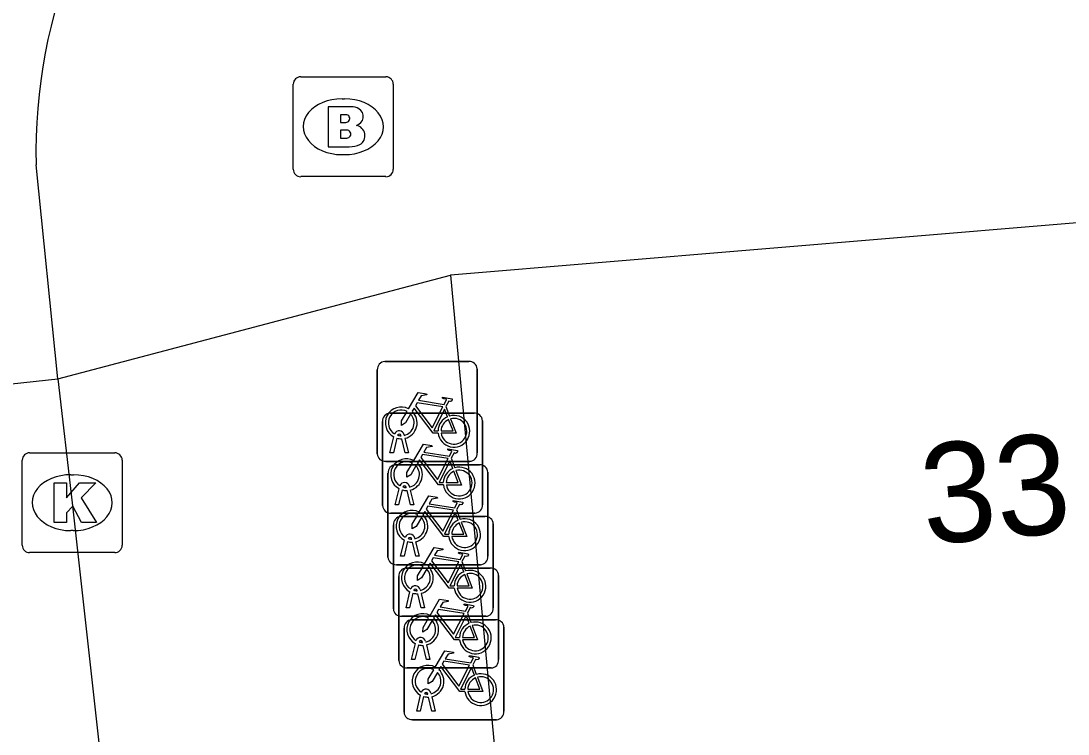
# Model space of a CAD drawing. Extents: x 159961 to 160856, y 382704 to 383353.
# Drawn here: x 160072.17 to 160082.65, y 383277.5 to 383284.64 of the extents above; entities that cross this region are included whole.
import ezdxf

# ---------------------------------------------------------------- set-up
doc = ezdxf.new("R2010")
doc.units = 0
for name, color, linetype in [('IMGEO_Brandkraan', 7, 'Continuous'), ('IMGEO_Fietsenrek', 7, 'Continuous'), ('IMGEO_Kolk', 7, 'Continuous'), ('IMGEO_Pand', 7, 'Continuous'), ('IMGEO_Pand_nummerreeks', 7, 'Continuous'), ('IMGEO_Rijbaan_lokaal_open', 7, 'Continuous'), ('IMGEO_Voetpad_open', 7, 'Continuous')]:
    doc.layers.add(name, color=color, linetype=linetype)

msp = doc.modelspace()

# ---------------------------------------------------------------- linework, layer by layer
at = {"layer": 'IMGEO_Brandkraan'}
for p, q in [((160074.897, 383283.157), (160074.897, 383284.009)), ((160074.972, 383284.083), (160075.824, 383284.083)), ((160075.898, 383284.009), (160075.898, 383283.157)), ((160075.385, 383283.863), (160075.41, 383283.863)), ((160075.408, 383283.303), (160075.383, 383283.303)), ((160075.824, 383283.083), (160074.972, 383283.083))]:
    msp.add_line(p, q, dxfattribs=at)
for points in [[(160074.897, 383283.157), (160074.897, 383284.009)], [(160074.972, 383284.083), (160075.824, 383284.083)], [(160075.898, 383284.009), (160075.898, 383283.157)], [(160075.245, 383283.783), (160075.245, 383283.383), (160075.458, 383283.383)], [(160075.476, 383283.783), (160075.245, 383283.783)], [(160075.424, 383283.702), (160075.37, 383283.702), (160075.37, 383283.626)], [(160075.37, 383283.626), (160075.423, 383283.626)], [(160075.432, 383283.55), (160075.37, 383283.55), (160075.37, 383283.469)], [(160075.37, 383283.469), (160075.432, 383283.469)], [(160075.824, 383283.083), (160074.972, 383283.083)]]:
    msp.add_lwpolyline(points, dxfattribs=at)
for centre, radius, start, end in [((160074.974, 383284.007), 0.0765, 91.552, 178.448), ((160074.974, 383284.007), 0.0765, 91.552, 178.448), ((160075.822, 383284.007), 0.0765, 1.552, 88.448), ((160075.822, 383284.007), 0.0765, 1.552, 88.448), ((160075.425, 383283.664), 0.0379, 267.8285, 90.9355), ((160075.48, 383283.638), 0.145, 59.4692, 91.5367), ((160075.505, 383283.685), 0.0922, 285.5137, 58.1501), ((160075.51, 383283.493), 0.105, 301.3115, 78.989), ((160075.433, 383283.509), 0.0404, 269.8759, 90.5077), ((160075.464, 383283.634), 0.251, 268.6676, 293.5347), ((160074.974, 383283.159), 0.0765, 181.552, 268.448), ((160074.974, 383283.159), 0.0765, 181.552, 268.448), ((160075.822, 383283.159), 0.0765, 271.552, 358.448), ((160075.822, 383283.159), 0.0765, 271.552, 358.448)]:
    msp.add_arc(centre, radius, start, end, dxfattribs=at)
for centre, major_axis, ratio, start_param, end_param in [((160075.384, 383283.583), (-0.387, 0.002), 0.722429, 4.712389, 7.853982), ((160075.409, 383283.583), (-0.39, 0.002), 0.717154, 1.570796, 4.712389)]:
    msp.add_ellipse(centre, major_axis=major_axis, ratio=ratio, start_param=start_param, end_param=end_param, dxfattribs=at)
at = {"layer": 'IMGEO_Fietsenrek'}
for p, q in [((160075.813, 383281.232), (160076.654, 383281.232)), ((160076.654, 383281.232), (160075.813, 383281.232)), ((160075.738, 383280.307), (160075.738, 383281.148)), ((160075.738, 383281.148), (160075.738, 383280.307)), ((160076.738, 383281.157), (160076.738, 383280.316)), ((160076.738, 383280.316), (160076.738, 383281.157)), ((160076.425, 383280.781), (160076.461, 383280.686)), ((160075.866, 383280.714), (160076.707, 383280.714)), ((160076.707, 383280.714), (160075.866, 383280.714)), ((160075.791, 383279.789), (160075.791, 383280.63)), ((160075.791, 383280.63), (160075.791, 383279.789)), ((160076.791, 383280.639), (160076.791, 383279.798)), ((160076.791, 383279.798), (160076.791, 383280.639)), ((160075.865, 383280.316), (160075.904, 383280.476)), ((160075.934, 383280.464), (160075.899, 383280.316)), ((160075.976, 383280.488), (160075.975, 383280.492)), ((160076.017, 383280.316), (160075.983, 383280.458)), ((160076.007, 383280.499), (160076.008, 383280.492)), ((160076.015, 383280.462), (160076.05, 383280.316)), ((160075.899, 383280.316), (160075.865, 383280.316)), ((160076.05, 383280.316), (160076.017, 383280.316)), ((160076.478, 383280.263), (160076.514, 383280.168)), ((160076.663, 383280.232), (160075.822, 383280.232)), ((160075.822, 383280.232), (160076.663, 383280.232)), ((160075.92, 383280.197), (160076.761, 383280.197)), ((160076.761, 383280.197), (160075.92, 383280.197)), ((160075.845, 383279.272), (160075.845, 383280.113)), ((160075.845, 383280.113), (160075.845, 383279.272)), ((160076.845, 383280.122), (160076.845, 383279.281)), ((160076.845, 383279.281), (160076.845, 383280.122)), ((160075.918, 383279.798), (160075.957, 383279.958)), ((160075.987, 383279.946), (160075.952, 383279.798)), ((160076.029, 383279.97), (160076.028, 383279.974)), ((160076.07, 383279.798), (160076.036, 383279.94)), ((160076.06, 383279.981), (160076.061, 383279.974)), ((160076.068, 383279.944), (160076.103, 383279.798)), ((160076.716, 383279.714), (160075.875, 383279.714)), ((160075.875, 383279.714), (160076.716, 383279.714)), ((160075.952, 383279.798), (160075.918, 383279.798)), ((160076.103, 383279.798), (160076.07, 383279.798)), ((160076.532, 383279.746), (160076.568, 383279.651)), ((160075.974, 383279.68), (160076.815, 383279.68)), ((160076.815, 383279.68), (160075.974, 383279.68)), ((160076.899, 383279.605), (160076.899, 383278.764)), ((160076.899, 383278.764), (160076.899, 383279.605)), ((160075.899, 383278.755), (160075.899, 383279.596)), ((160075.899, 383279.596), (160075.899, 383278.755)), ((160075.972, 383279.281), (160076.011, 383279.441)), ((160076.041, 383279.429), (160076.006, 383279.281)), ((160076.083, 383279.453), (160076.082, 383279.457)), ((160076.124, 383279.281), (160076.09, 383279.423)), ((160076.114, 383279.464), (160076.115, 383279.457)), ((160076.122, 383279.427), (160076.157, 383279.281)), ((160076.77, 383279.197), (160075.929, 383279.197)), ((160075.929, 383279.197), (160076.77, 383279.197)), ((160076.006, 383279.281), (160075.972, 383279.281)), ((160076.157, 383279.281), (160076.124, 383279.281)), ((160076.586, 383279.229), (160076.622, 383279.134)), ((160076.028, 383279.163), (160076.869, 383279.163)), ((160076.869, 383279.163), (160076.028, 383279.163)), ((160076.953, 383279.088), (160076.953, 383278.247)), ((160076.953, 383278.247), (160076.953, 383279.088)), ((160075.953, 383278.238), (160075.953, 383279.079)), ((160075.953, 383279.079), (160075.953, 383278.238)), ((160076.026, 383278.764), (160076.065, 383278.924)), ((160076.095, 383278.912), (160076.06, 383278.764)), ((160076.137, 383278.936), (160076.136, 383278.94)), ((160076.178, 383278.764), (160076.144, 383278.906)), ((160076.168, 383278.947), (160076.169, 383278.94)), ((160076.176, 383278.91), (160076.211, 383278.764)), ((160076.824, 383278.68), (160075.983, 383278.68)), ((160075.983, 383278.68), (160076.824, 383278.68)), ((160076.06, 383278.764), (160076.026, 383278.764)), ((160076.211, 383278.764), (160076.178, 383278.764)), ((160076.64, 383278.712), (160076.676, 383278.617)), ((160076.006, 383277.72), (160076.006, 383278.561)), ((160076.006, 383278.561), (160076.006, 383277.72)), ((160076.081, 383278.645), (160076.922, 383278.645)), ((160076.922, 383278.645), (160076.081, 383278.645)), ((160077.006, 383278.57), (160077.006, 383277.729)), ((160077.006, 383277.729), (160077.006, 383278.57)), ((160076.08, 383278.247), (160076.119, 383278.407)), ((160076.149, 383278.395), (160076.114, 383278.247)), ((160076.191, 383278.419), (160076.19, 383278.423)), ((160076.232, 383278.247), (160076.198, 383278.389)), ((160076.222, 383278.43), (160076.223, 383278.423)), ((160076.23, 383278.393), (160076.265, 383278.247)), ((160076.114, 383278.247), (160076.08, 383278.247)), ((160076.265, 383278.247), (160076.232, 383278.247)), ((160076.878, 383278.163), (160076.037, 383278.163)), ((160076.037, 383278.163), (160076.878, 383278.163)), ((160076.693, 383278.194), (160076.729, 383278.099)), ((160076.133, 383277.729), (160076.172, 383277.889)), ((160076.202, 383277.877), (160076.167, 383277.729)), ((160076.244, 383277.901), (160076.243, 383277.905)), ((160076.285, 383277.729), (160076.251, 383277.871)), ((160076.275, 383277.912), (160076.276, 383277.905)), ((160076.283, 383277.875), (160076.318, 383277.729)), ((160076.167, 383277.729), (160076.133, 383277.729)), ((160076.318, 383277.729), (160076.285, 383277.729)), ((160076.931, 383277.645), (160076.09, 383277.645)), ((160076.09, 383277.645), (160076.931, 383277.645))]:
    msp.add_line(p, q, dxfattribs=at)
for points in [[(160076.051, 383280.758), (160076.146, 383280.922), (160076.232, 383280.908), (160076.234, 383280.899), (160076.178, 383280.888), (160076.151, 383280.843), (160076.407, 383280.802)], [(160076.407, 383280.802), (160076.432, 383280.851), (160076.426, 383280.855), (160076.403, 383280.859), (160076.391, 383280.866), (160076.39, 383280.869), (160076.392, 383280.874), (160076.487, 383280.859), (160076.489, 383280.849), (160076.479, 383280.836), (160076.467, 383280.83), (160076.453, 383280.836), (160076.425, 383280.781)], [(160076.347, 383280.514), (160076.297, 383280.514), (160076.106, 383280.765), (160076.087, 383280.733)], [(160076.394, 383280.777), (160076.137, 383280.818), (160076.12, 383280.789), (160076.287, 383280.569), (160076.394, 383280.777)], [(160076.072, 383280.706), (160076.02, 383280.616), (160075.98, 383280.591), (160075.981, 383280.638), (160076.036, 383280.732)], [(160076.442, 383280.679), (160076.412, 383280.756), (160076.303, 383280.538), (160076.346, 383280.538)], [(160076.472, 383280.658), (160076.527, 383280.513), (160076.377, 383280.513)], [(160076.376, 383280.538), (160076.496, 383280.537), (160076.452, 383280.651)], [(160076.104, 383280.24), (160076.199, 383280.404), (160076.285, 383280.39), (160076.287, 383280.381), (160076.231, 383280.37), (160076.204, 383280.325), (160076.46, 383280.284)], [(160076.46, 383280.284), (160076.485, 383280.333), (160076.479, 383280.337), (160076.456, 383280.341), (160076.444, 383280.348), (160076.443, 383280.351), (160076.445, 383280.356), (160076.54, 383280.341), (160076.542, 383280.331), (160076.532, 383280.318), (160076.52, 383280.312), (160076.506, 383280.318), (160076.478, 383280.263)], [(160076.4, 383279.996), (160076.35, 383279.996), (160076.159, 383280.247), (160076.14, 383280.215)], [(160076.447, 383280.259), (160076.19, 383280.3), (160076.173, 383280.271), (160076.34, 383280.051), (160076.447, 383280.259)], [(160076.495, 383280.161), (160076.465, 383280.238), (160076.356, 383280.02), (160076.399, 383280.02)], [(160076.125, 383280.188), (160076.073, 383280.098), (160076.033, 383280.073), (160076.034, 383280.12), (160076.089, 383280.214)], [(160076.429, 383280.02), (160076.549, 383280.019), (160076.505, 383280.133)], [(160076.525, 383280.14), (160076.58, 383279.995), (160076.43, 383279.995)], [(160076.158, 383279.723), (160076.253, 383279.887), (160076.339, 383279.873), (160076.341, 383279.864), (160076.285, 383279.853), (160076.258, 383279.808), (160076.514, 383279.767)], [(160076.514, 383279.767), (160076.539, 383279.816), (160076.533, 383279.82), (160076.51, 383279.824), (160076.498, 383279.831), (160076.497, 383279.834), (160076.499, 383279.839), (160076.594, 383279.824), (160076.596, 383279.814), (160076.586, 383279.801), (160076.574, 383279.795), (160076.56, 383279.801), (160076.532, 383279.746)], [(160076.454, 383279.479), (160076.404, 383279.479), (160076.213, 383279.73), (160076.194, 383279.698)], [(160076.501, 383279.742), (160076.244, 383279.783), (160076.227, 383279.754), (160076.394, 383279.534), (160076.501, 383279.742)], [(160076.549, 383279.644), (160076.519, 383279.721), (160076.41, 383279.503), (160076.453, 383279.503)], [(160076.179, 383279.671), (160076.127, 383279.581), (160076.087, 383279.556), (160076.088, 383279.603), (160076.143, 383279.697)], [(160076.483, 383279.503), (160076.603, 383279.502), (160076.559, 383279.616)], [(160076.579, 383279.623), (160076.634, 383279.478), (160076.484, 383279.478)], [(160076.212, 383279.206), (160076.307, 383279.37), (160076.393, 383279.356), (160076.395, 383279.347), (160076.339, 383279.336), (160076.312, 383279.291), (160076.568, 383279.25)], [(160076.568, 383279.25), (160076.593, 383279.299), (160076.587, 383279.303), (160076.564, 383279.307), (160076.552, 383279.314), (160076.551, 383279.317), (160076.553, 383279.322), (160076.648, 383279.307), (160076.65, 383279.297), (160076.64, 383279.284), (160076.628, 383279.278), (160076.614, 383279.284), (160076.586, 383279.229)], [(160076.508, 383278.962), (160076.458, 383278.962), (160076.267, 383279.213), (160076.248, 383279.181)], [(160076.555, 383279.225), (160076.298, 383279.266), (160076.281, 383279.237), (160076.448, 383279.017), (160076.555, 383279.225)], [(160076.603, 383279.127), (160076.573, 383279.204), (160076.464, 383278.986), (160076.507, 383278.986)], [(160076.233, 383279.154), (160076.181, 383279.064), (160076.141, 383279.039), (160076.142, 383279.086), (160076.197, 383279.18)], [(160076.537, 383278.986), (160076.657, 383278.985), (160076.613, 383279.099)], [(160076.633, 383279.106), (160076.688, 383278.961), (160076.538, 383278.961)], [(160076.266, 383278.689), (160076.361, 383278.853), (160076.447, 383278.839), (160076.449, 383278.83), (160076.393, 383278.819), (160076.366, 383278.774), (160076.622, 383278.733)], [(160076.622, 383278.733), (160076.647, 383278.782), (160076.641, 383278.786), (160076.618, 383278.79), (160076.606, 383278.797), (160076.605, 383278.8), (160076.607, 383278.805), (160076.702, 383278.79), (160076.704, 383278.78), (160076.694, 383278.767), (160076.682, 383278.761), (160076.668, 383278.767), (160076.64, 383278.712)], [(160076.287, 383278.637), (160076.235, 383278.547), (160076.195, 383278.522), (160076.196, 383278.569), (160076.251, 383278.663)], [(160076.562, 383278.445), (160076.512, 383278.445), (160076.321, 383278.696), (160076.302, 383278.664)], [(160076.609, 383278.708), (160076.352, 383278.749), (160076.335, 383278.72), (160076.502, 383278.5), (160076.609, 383278.708)], [(160076.657, 383278.61), (160076.627, 383278.687), (160076.518, 383278.469), (160076.561, 383278.469)], [(160076.591, 383278.469), (160076.711, 383278.468), (160076.667, 383278.582)], [(160076.687, 383278.589), (160076.742, 383278.444), (160076.592, 383278.444)], [(160076.319, 383278.171), (160076.414, 383278.335), (160076.5, 383278.321), (160076.502, 383278.312), (160076.446, 383278.301), (160076.419, 383278.256), (160076.675, 383278.215)], [(160076.675, 383278.215), (160076.7, 383278.264), (160076.694, 383278.268), (160076.671, 383278.272), (160076.659, 383278.279), (160076.658, 383278.282), (160076.66, 383278.287), (160076.755, 383278.272), (160076.757, 383278.262), (160076.747, 383278.249), (160076.735, 383278.243), (160076.721, 383278.249), (160076.693, 383278.194)], [(160076.34, 383278.119), (160076.288, 383278.029), (160076.248, 383278.004), (160076.249, 383278.051), (160076.304, 383278.145)], [(160076.615, 383277.927), (160076.565, 383277.927), (160076.374, 383278.178), (160076.355, 383278.146)], [(160076.662, 383278.19), (160076.405, 383278.231), (160076.388, 383278.202), (160076.555, 383277.982), (160076.662, 383278.19)], [(160076.71, 383278.092), (160076.68, 383278.169), (160076.571, 383277.951), (160076.614, 383277.951)], [(160076.644, 383277.951), (160076.764, 383277.95), (160076.72, 383278.064)], [(160076.74, 383278.071), (160076.795, 383277.926), (160076.645, 383277.926)]]:
    msp.add_lwpolyline(points, dxfattribs=at)
for centre, radius, start, end in [((160075.816, 383281.154), 0.0779, 92.4484, 184.2845), ((160075.816, 383281.154), 0.0779, 92.4484, 184.2845), ((160076.66, 383281.154), 0.0779, 2.4484, 94.2845), ((160076.66, 383281.154), 0.0779, 2.4484, 94.2845), ((160075.978, 383280.617), 0.159, 62.6766, 242.1369), ((160075.869, 383280.636), 0.0779, 92.4484, 184.2845), ((160075.869, 383280.636), 0.0779, 92.4484, 184.2845), ((160075.978, 383280.617), 0.129, 63.3192, 238.903), ((160075.978, 383280.617), 0.129, 283.6043, 43.4302), ((160075.978, 383280.617), 0.159, 283.5766, 46.6042), ((160076.505, 383280.533), 0.159, 113.3408, 178.3217), ((160076.505, 383280.533), 0.159, 187.0065, 105.7708), ((160076.505, 383280.533), 0.129, 188.6715, 104.5883), ((160076.713, 383280.636), 0.0779, 2.4484, 94.2845), ((160076.713, 383280.636), 0.0779, 2.4484, 94.2845), ((160076.505, 383280.533), 0.129, 113.923, 177.9556), ((160075.958, 383280.488), 0.0499, 12.8025, 158.6934), ((160075.978, 383280.617), 0.159, 253.9967, 271.7867), ((160075.958, 383280.488), 0.0174, 12.8025, 163.4502), ((160075.978, 383280.617), 0.129, 253.415, 269.0204), ((160075.816, 383280.31), 0.0779, 182.4484, 274.2845), ((160075.816, 383280.31), 0.0779, 182.4484, 274.2845), ((160076.031, 383280.099), 0.159, 62.6766, 242.1369), ((160076.66, 383280.31), 0.0779, 272.4484, 4.2845), ((160076.66, 383280.31), 0.0779, 272.4484, 4.2845), ((160075.923, 383280.119), 0.0779, 92.4484, 184.2845), ((160075.923, 383280.119), 0.0779, 92.4484, 184.2845), ((160076.031, 383280.099), 0.129, 63.3192, 238.903), ((160076.031, 383280.099), 0.129, 283.6043, 43.4302), ((160076.031, 383280.099), 0.159, 283.5766, 46.6042), ((160076.558, 383280.015), 0.159, 113.3408, 178.3217), ((160076.558, 383280.015), 0.159, 187.0065, 105.7708), ((160076.558, 383280.015), 0.129, 113.923, 177.9556), ((160076.558, 383280.015), 0.129, 188.6715, 104.5883), ((160076.767, 383280.119), 0.0779, 2.4484, 94.2845), ((160076.767, 383280.119), 0.0779, 2.4484, 94.2845), ((160076.011, 383279.97), 0.0499, 12.8025, 158.6934), ((160076.031, 383280.099), 0.159, 253.9967, 271.7867), ((160076.011, 383279.97), 0.0174, 12.8025, 163.4502), ((160076.031, 383280.099), 0.129, 253.415, 269.0204), ((160075.869, 383279.792), 0.0779, 182.4484, 274.2845), ((160075.869, 383279.792), 0.0779, 182.4484, 274.2845), ((160076.085, 383279.582), 0.159, 62.6766, 242.1369), ((160076.085, 383279.582), 0.129, 63.3192, 238.903), ((160076.713, 383279.792), 0.0779, 272.4484, 4.2845), ((160076.713, 383279.792), 0.0779, 272.4484, 4.2845), ((160075.977, 383279.602), 0.0779, 92.4484, 184.2845), ((160075.977, 383279.602), 0.0779, 92.4484, 184.2845), ((160076.085, 383279.582), 0.129, 283.6043, 43.4302), ((160076.085, 383279.582), 0.159, 283.5766, 46.6042), ((160076.612, 383279.498), 0.159, 113.3408, 178.3217), ((160076.612, 383279.498), 0.159, 187.0065, 105.7708), ((160076.612, 383279.498), 0.129, 113.923, 177.9556), ((160076.612, 383279.498), 0.129, 188.6715, 104.5883), ((160076.821, 383279.602), 0.0779, 2.4484, 94.2845), ((160076.821, 383279.602), 0.0779, 2.4484, 94.2845), ((160076.065, 383279.453), 0.0499, 12.8025, 158.6934), ((160076.085, 383279.582), 0.159, 253.9967, 271.7867), ((160076.065, 383279.453), 0.0174, 12.8025, 163.4502), ((160076.085, 383279.582), 0.129, 253.415, 269.0204), ((160075.923, 383279.275), 0.0779, 182.4484, 274.2845), ((160075.923, 383279.275), 0.0779, 182.4484, 274.2845), ((160076.139, 383279.065), 0.159, 62.6766, 242.1369), ((160076.139, 383279.065), 0.129, 63.3192, 238.903), ((160076.767, 383279.275), 0.0779, 272.4484, 4.2845), ((160076.767, 383279.275), 0.0779, 272.4484, 4.2845), ((160076.031, 383279.085), 0.0779, 92.4484, 184.2845), ((160076.031, 383279.085), 0.0779, 92.4484, 184.2845), ((160076.139, 383279.065), 0.129, 283.6043, 43.4302), ((160076.139, 383279.065), 0.159, 283.5766, 46.6042), ((160076.666, 383278.981), 0.159, 113.3408, 178.3217), ((160076.666, 383278.981), 0.159, 187.0065, 105.7708), ((160076.666, 383278.981), 0.129, 113.923, 177.9556), ((160076.666, 383278.981), 0.129, 188.6715, 104.5883), ((160076.875, 383279.085), 0.0779, 2.4484, 94.2845), ((160076.875, 383279.085), 0.0779, 2.4484, 94.2845), ((160076.119, 383278.936), 0.0499, 12.8025, 158.6934), ((160076.139, 383279.065), 0.159, 253.9967, 271.7867), ((160076.119, 383278.936), 0.0174, 12.8025, 163.4502), ((160076.139, 383279.065), 0.129, 253.415, 269.0204), ((160075.977, 383278.758), 0.0779, 182.4484, 274.2845), ((160075.977, 383278.758), 0.0779, 182.4484, 274.2845), ((160076.193, 383278.548), 0.159, 62.6766, 242.1369), ((160076.193, 383278.548), 0.129, 63.3192, 238.903), ((160076.193, 383278.548), 0.159, 283.5766, 46.6042), ((160076.821, 383278.758), 0.0779, 272.4484, 4.2845), ((160076.821, 383278.758), 0.0779, 272.4484, 4.2845), ((160076.084, 383278.567), 0.0779, 92.4484, 184.2845), ((160076.084, 383278.567), 0.0779, 92.4484, 184.2845), ((160076.193, 383278.548), 0.129, 283.6043, 43.4302), ((160076.72, 383278.464), 0.159, 113.3408, 178.3217), ((160076.72, 383278.464), 0.159, 187.0065, 105.7708), ((160076.72, 383278.464), 0.129, 113.923, 177.9556), ((160076.72, 383278.464), 0.129, 188.6715, 104.5883), ((160076.928, 383278.567), 0.0779, 2.4484, 94.2845), ((160076.928, 383278.567), 0.0779, 2.4484, 94.2845), ((160076.173, 383278.419), 0.0499, 12.8025, 158.6934), ((160076.193, 383278.548), 0.159, 253.9967, 271.7867), ((160076.173, 383278.419), 0.0174, 12.8025, 163.4502), ((160076.193, 383278.548), 0.129, 253.415, 269.0204), ((160076.875, 383278.241), 0.0779, 272.4484, 4.2845), ((160076.875, 383278.241), 0.0779, 272.4484, 4.2845), ((160076.031, 383278.241), 0.0779, 182.4484, 274.2845), ((160076.031, 383278.241), 0.0779, 182.4484, 274.2845), ((160076.246, 383278.03), 0.159, 62.6766, 242.1369), ((160076.246, 383278.03), 0.129, 63.3192, 238.903), ((160076.246, 383278.03), 0.159, 283.5766, 46.6042), ((160076.246, 383278.03), 0.129, 283.6043, 43.4302), ((160076.773, 383277.946), 0.159, 113.3408, 178.3217), ((160076.773, 383277.946), 0.159, 187.0065, 105.7708), ((160076.773, 383277.946), 0.129, 113.923, 177.9556), ((160076.773, 383277.946), 0.129, 188.6715, 104.5883), ((160076.226, 383277.901), 0.0499, 12.8025, 158.6934), ((160076.246, 383278.03), 0.159, 253.9967, 271.7867), ((160076.226, 383277.901), 0.0174, 12.8025, 163.4502), ((160076.246, 383278.03), 0.129, 253.415, 269.0204), ((160076.084, 383277.723), 0.0779, 182.4484, 274.2845), ((160076.084, 383277.723), 0.0779, 182.4484, 274.2845), ((160076.928, 383277.723), 0.0779, 272.4484, 4.2845), ((160076.928, 383277.723), 0.0779, 272.4484, 4.2845)]:
    msp.add_arc(centre, radius, start, end, dxfattribs=at)
at = {"layer": 'IMGEO_Kolk'}
for p, q in [((160072.183, 383279.392), (160072.183, 383280.244)), ((160072.258, 383280.318), (160073.11, 383280.318)), ((160073.184, 383280.244), (160073.184, 383279.392)), ((160072.671, 383280.098), (160072.696, 383280.098)), ((160072.694, 383279.538), (160072.669, 383279.538)), ((160073.11, 383279.318), (160072.258, 383279.318))]:
    msp.add_line(p, q, dxfattribs=at)
for points in [[(160072.183, 383279.392), (160072.183, 383280.244)], [(160072.258, 383280.318), (160073.11, 383280.318)], [(160073.184, 383280.244), (160073.184, 383279.392)], [(160072.504, 383280.018), (160072.627, 383280.018), (160072.627, 383279.867), (160072.757, 383280.018), (160072.921, 383280.018), (160072.775, 383279.867), (160072.928, 383279.618), (160072.776, 383279.618), (160072.691, 383279.782), (160072.627, 383279.715), (160072.627, 383279.618), (160072.504, 383279.618), (160072.504, 383280.018)], [(160073.11, 383279.318), (160072.258, 383279.318)]]:
    msp.add_lwpolyline(points, dxfattribs=at)
for centre, start, end in [((160072.26, 383280.242), 91.552, 178.448), ((160072.26, 383280.242), 91.552, 178.448), ((160073.108, 383280.242), 1.552, 88.448), ((160073.108, 383280.242), 1.552, 88.448), ((160072.26, 383279.394), 181.552, 268.448), ((160072.26, 383279.394), 181.552, 268.448), ((160073.108, 383279.394), 271.552, 358.448), ((160073.108, 383279.394), 271.552, 358.448)]:
    msp.add_arc(centre, 0.0765, start, end, dxfattribs=at)
for centre, major_axis, ratio, start_param, end_param in [((160072.67, 383279.818), (-0.387, 0.002), 0.722429, 4.712389, 7.853982), ((160072.695, 383279.818), (-0.39, 0.002), 0.717154, 1.570796, 4.712389)]:
    msp.add_ellipse(centre, major_axis=major_axis, ratio=ratio, start_param=start_param, end_param=end_param, dxfattribs=at)
at = {"layer": 'IMGEO_Pand'}
for points in [[(160087.099, 383282.985), (160076.472, 383282.097)], [(160076.472, 383282.097), (160077.135, 383274.96), (160078.039, 383266.783)]]:
    msp.add_lwpolyline(points, dxfattribs=at)
at = {"layer": 'IMGEO_Rijbaan_lokaal_open'}
for points in [[(160072.54, 383281.057), (160072.322, 383283.202)], [(160066.298, 383280.383), (160072.54, 383281.057)], [(160072.54, 383281.057), (160072.684, 383279.818), (160073.105, 383276.032)]]:
    msp.add_lwpolyline(points, dxfattribs=at)
msp.add_arc((160077.839, 383283.308), 5.518, 88.3758, 181.0966, dxfattribs=at)
at = {"layer": 'IMGEO_Voetpad_open'}
msp.add_lwpolyline([(160072.54, 383281.057), (160076.472, 383282.097)], dxfattribs=at)

# ---------------------------------------------------------------- texts
at = {"layer": 'IMGEO_Pand_nummerreeks'}
msp.add_text('33', height=1, rotation=5.1222, dxfattribs=at).set_placement((160081.225, 383279.396))

doc.saveas('drawing.dxf')
